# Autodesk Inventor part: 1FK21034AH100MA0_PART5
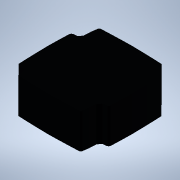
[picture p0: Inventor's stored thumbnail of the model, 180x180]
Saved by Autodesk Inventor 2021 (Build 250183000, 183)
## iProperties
Created: 2025-04
Part Number: 1FK21034AH100MA0_PART5
Material: Generic
Catalog Web Link: www.3dfindit.com
Description: -Servo synchronous motor
Document SubType Name: Modeling
Designer: psAdmin
Mass: 81.3964 g
Surface Area: 120.819 cm^2
Volume: 81.3964 cm^3
Density: 1 g/cm^3
Appearance: PSOLRGB-38-46-56
Category: PARTsolutions
Title: 1FK21034AH100MA0_PART5
Author: Cadenas PARTsolutions
Comments: Servo synchronous motor
Sending System: PARTsolutions
Preprocessor: ST-DEVELOPER v19.3
PSOL_IDENT_0: {$CADENAS_DATA/23d-libs/siemens_ag/_cat_/39/97/1fk21034ah100ma0.prj},213 {VTYP=3D},{NB=1FK21034AH100
PSOL_IDENT_1: MA0_PART5},{LINA=1FK21034AH100MA0_PART5},{NN=1FK21034AH100MA0_PART5},{NOPRJ=TRUE},{DATE=19.08.2025 1
PSOL_IDENT_2: 4:00:33},{GEOMDATE=30.07.2025 02:02:21},{VERSION=},{LINEID=10},{WBVAR=},{WBNUMERIC=}  {NB=1FK21034AH
PSOL_IDENT_3: 100MA0_PART5},{LINA=1FK21034AH100MA0_PART5},{KT=DUMMY},{PREVIEW=../../../_pool_/d3/78/p_d211_xx_0093
PSOL_IDENT_4: 4j.png},{DESCSHORT=SIMOTICS S-1FK2 HD, SINAMICS S210 3AC 400V-480V, 1.01 Nm, 4500 rpm},{DESCLONG=SIM
PSOL_IDENT_5: OTICS S-1FK2 HD servo motor M0=1.27 Nm; PN = 0.48 kW at nN=4500 rpm (380-480 V); PN = 0.3 kW at nN=2
PSOL_IDENT_6: 500 rpm (200-240 V); with holding brake; degree of protection IP64; cylindrical shaft D14 x 30 mm; a
PSOL_IDENT_7: bsolute encoder 22-bit + 12-bit multiturn (encoder AM22DQC); with OCC interface; plug size M17, rota
PSOL_IDENT_8: table; SIMOTICS S-1FK2 servomotorfor a wide range of uses in industrial environments. SIMOTICS S‑1FK
PSOL_IDENT_9: 2 servomotors are compact synchronous motors with a high dynamic performance that set themselves apa
PSOL_IDENT_10: rt as a result of their high power density, degree of protection and overload capability. The motors
PSOL_IDENT_11: are available in two variants: as High Dynamic variant (highest dynamic performance as a result of
PSOL_IDENT_12: the low intrinsic moment of inertia for applications demanding a high dynamic performance with low m
PSOL_IDENT_13: oved masses) - and as Compact variant (precise and stable closed-loop control for medium up to large
PSOL_IDENT_14: moved masses as a result of a medium intrinsic moment of inertia). SIMOTICSS‑1FK2 servomotors fully
PSOL_IDENT_15: exploit their strengths in a system with the SINAMICSS210 frequency converter and simple connection
PSOL_IDENT_16: using the one cable connection (OCC). Advantages include the short control and positioning times, f
PSOL_IDENT_17: ast and precise correction of disturbing quantities as well as stable control with a high dynamic pe
PSOL_IDENT_18: rformance. The servo motors can be configured to address a wide range of requirements. For example w
PSOL_IDENT_19: ith and without holding brake, IP64 or IP65 degree of protection, singleturn or multiturn absolute e
PSOL_IDENT_20: ncoders - to name just a few. Further, the servomotors are available in different shaft heights exte
PSOL_IDENT_21: nding from 20 to 100. A shaft sealing ring is available to achieve an IP65 degree of protection and
PSOL_IDENT_22: for subsequent mounting at the motor or as spare part. SIMOTICS - the optimum motor for each and eve
PSOL_IDENT_23: ry motion control application.},{INTNO=195125454019},{SUPPLIERALTNO=1FK2103-4AH10-0MA0},{MANUID=1FK2
PSOL_IDENT_24: 1034AH100MA0},{MANUNAME=Siemens},{MANUTYPEDESC=SYNCHRONOUS MOTOR 1FK2 HD 1,27 NM},{AAU732=SIMOTICS},
PSOL_IDENT_25: {AAO057=S-1FK2},{AAU734=SIMOTICS S-1FK2 HD servo motor M0=1.27 Nm; PN = 0.48 kW at nN=4500 rpm (380-
PSOL_IDENT_26: 480 V); PN = 0.3 kW at nN=2500 rpm (200-240 V); with holding brake; degree of protection IP64; cylin
PSOL_IDENT_27: drical shaft D14 x 30 mm; absolute encoder 22-bit + 12-bit multiturn (encoder AM22DQC); with OCC int
PSOL_IDENT_28: erface; plug size M17, rotatable;},{AAW338=SYNCHRONOUS MOTOR 1FK2 HD 1,27 NM},{AAO742=SIMOTICS},{AAO
PSOL_IDENT_29: 663=4034106444921},{NOCUPEROU=1},{PRICEQUANTITY=1},{QUANTITYMIN=1},{QUANTITYINT=1},{CTN=85015100},{C
PSOL_IDENT_30: OO=RO},{AAO676=1FK2103-4AH10-0MA0},{AAO677=Siemens AG},{ORDERUNIT=C62},{CONTENTUNIT=C62}
NB: 1FK21034AH100MA0_PART5
NT: Servo synchronous motor
NBSYN: $MANUID._PART5
LINA: 1FK21034AH100MA0_PART5
CATALOG: SIEMENS
PREVIEW: ../../../_pool_/d3/78/p_d211_xx_00934j.png
DESCSHORT: SIMOTICS S-1FK2 HD, SINAMICS S210 3AC 400V-480V, 1.01 Nm, 4500 rpm
DESCLONG: SIMOTICS S-1FK2 HD servo motor M0=1.27 Nm; PN = 0.48 kW at nN=4500 rpm (380-480 V); PN = 0.3 kW at nN=2500 rpm (200-240 V); with holding brake; degree of protec
INTNO: 195125454019
SUPPLIERALTNO: 1FK2103-4AH10-0MA0
MANUID: 1FK21034AH100MA0
MANUNAME: Siemens
MANUTYPEDESC: SYNCHRONOUS MOTOR 1FK2 HD 1,27 NM
AAU732: SIMOTICS
AAO057: S-1FK2
AAU734: SIMOTICS S-1FK2 HD servo motor M0=1.27 Nm; PN = 0.48 kW at nN=4500 rpm (380-480 V); PN = 0.3 kW at nN=2500 rpm (200-240 V); with holding brake; degree of protec
AAW338: SYNCHRONOUS MOTOR 1FK2 HD 1,27 NM
AAO742: SIMOTICS
AAO663: 4034106444921.0
NOCUPEROU: 1
PRICEQUANTITY: 1
QUANTITYMIN: 1
QUANTITYINT: 1
CTN: 85015100
COO: RO
ARTICLENO: 1FK21034AH100MA0_PART5
BOMINFO: 1FK21034AH100MA0_PART5
CREATOR: CADENAS GmbH
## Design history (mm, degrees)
feature "2025_04_17_15_09_00_0268"
body "Solid1"
